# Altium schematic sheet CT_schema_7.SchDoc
size 287 x 160 mm
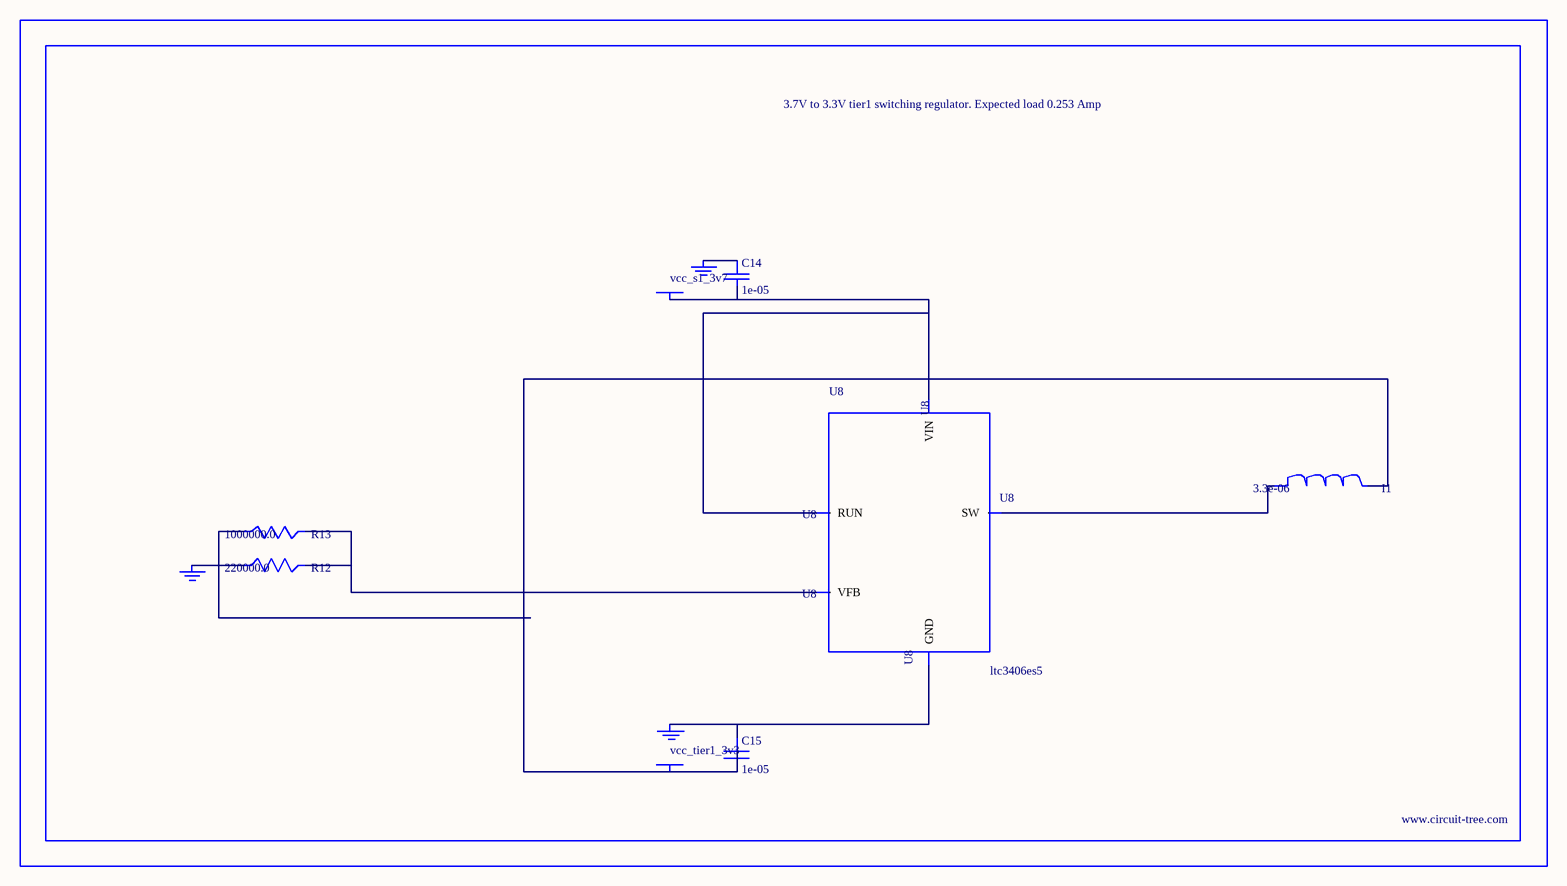
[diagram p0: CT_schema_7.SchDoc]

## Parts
BORDER6  (no value)
C14  1e-05  [C0805]
C15  1e-05  [C0805]
GND_INSTANCE_6_0  (no value)
GND_INSTANCE_6_1  (no value)
GND_INSTANCE_6_2  (no value)
I1  3.3e-06  [L0806]
POWER_INSTANCE_6_0  vcc_tier1_3v3
POWER_INSTANCE_6_1  vcc_s1_3v7
R12  220000.0  [R0603]
R13  1000000.0  [R0603]
U8  ltc3406es5  [TSOT-23-5]

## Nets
NetC14_1: C14.1 GND_INSTANCE_6_1.0(GND)
NetC14_2: C14.2 POWER_INSTANCE_6_1.0(PWR) U8.1(RUN) U8.4(VIN)
NetC15_1: C15.1 GND_INSTANCE_6_0.0(GND) U8.2(GND)
NetC15_2: C15.2 I1.2 POWER_INSTANCE_6_0.0(PWR) R13.1
NetGND_INSTANCE_6_2_0: GND_INSTANCE_6_2.0(GND) R12.1
NetI1_1: I1.1 U8.3(SW)
NetR12_2: R12.2 R13.2 U8.5(VFB)

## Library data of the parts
BORDER6 = BORDER_PAGE6
C14 C15 = C0805C106K8RACTU
GND_INSTANCE_6_0-GND_INSTANCE_6_2 = GND
I1 = L0806C3R3MDWIT
POWER_INSTANCE_6_0 POWER_INSTANCE_6_1 = PWR
R12 = RC0603JR-07220KL
R13 = RC0603JR-071ML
